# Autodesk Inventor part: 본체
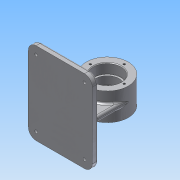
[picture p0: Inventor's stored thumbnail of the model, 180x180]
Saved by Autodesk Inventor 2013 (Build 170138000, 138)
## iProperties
Created: 2019-09
Part Number: 본체
Material: 알루미늄 6061
Document SubType Name: Modeling
Designer: Administrator
Density: 2.71 g/cm^3
Mass: 556.675 g
Surface Area: 495.884 cm^2
Volume: 205.415 cm^3
Author: Administrator
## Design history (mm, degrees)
sketch "스케치1"
  geometry: C1 r 32 at (0, 0); 1 further point
  constraints: 1 centre point, 1 coincident
  dimensions: "d0" = 64 diameter of C1
extrude "돌출1" new body sketch "스케치1" stored distance "d1" = 42; taper "d2" = 0 deg
hole "구멍1" diameter "d5" = 36; stored, may be unused: countersink angle "d9" = 90 deg, drill point angle "d11" = 118 deg; dims "d3" = 10, "d4" = 10, "d6" = 6, "d7" = 42, "d8" = 15, "d10" = 8
sketch "스케치2"
  geometry: C1 r 18 at (0, 0) reference; C2 r 32 at (0, 0) reference; C3 r 21 at (0, 0)
  constraints: 1 centre point, 1 coincident
  dimensions: "d12" = 42 diameter of C3
extrude "돌출2" cut sketch "스케치2" distance "d13" = 15; taper "d14" = 0 deg
fillet "모깎기1" dims "d15" = 0.3
chamfer "모따기1" distance "d16" = 1; stored, may be unused: second distance "d17" = 2, angle "d18" = 45 deg
sketch "스케치3"
  geometry: C1 r 32 at (0, 0) reference; 1 further point
  constraints: 1 vertical alignment
  dimensions: "d19" = 26 distance of C1.centre point (0, 26)
hole "구멍2" sketch "스케치3" at (0, 26) diameter "d20" = 3.242; stored, may be unused: countersink angle "d24" = 90 deg, drill point angle "d26" = 118 deg; dims "d21" = 8, "d22" = 42, "d23" = 15, "d25" = 10
node "작업 평면1"
sketch "스케치4"
  geometry: L1 (62, 63)-(-36, 63); L2 (-36, 63)-(-36, -63); L3 (-36, -63)-(62, -63); L4 (62, -63)-(62, 63); 2 further points
  constraints: 8 end point, 2 parallel, 1 horizontal, 1 horizontal alignment, 1 midpoint, 1 perpendicular
  dimensions: "d31" = 126 distance of L1.end L2.end; "d33" = 62 distance from line of L4 point (0, 0); "d34" = 98 distance of L2.end L3.end
extrude "돌출3" join sketch "스케치4" distance "d35" = 9; taper "d36" = 0 deg
sketch "스케치5"
  geometry: L1 (-32, -4)-(32, -4); L2 (32, -4)-(32, 4); L3 (32, 4)-(-32, 4); L4 (-32, 4)-(-32, -4); L5 (-4, -17)-(4, -17); L6 (4, -17)-(4, 17); L7 (4, 17)-(-4, 17); L8 (-4, 17)-(-4, -17); 3 further points
  constraints: 16 end point, 4 parallel, 2 horizontal, 2 midpoint, 2 perpendicular, 1 horizontal alignment, 1 vertical alignment
  dimensions: "d37" = 8 distance of L2.end L1.end; "d38" = 8 distance of L7.end L6.end; "d39" = 34 distance of L5.end L6.end; "d40" = 17 distance from line of point (0, 0) L5; "d41" = 64 distance of L2.end L3.end; "d56" = 32 distance from line of point (0, 0) L4
extrude "돌출4" join sketch "스케치5" stored distance "d43" = 9; taper "d44" = 0 deg
fillet "모깎기2" dims "d45" = 12
sketch "스케치6"
  geometry: A1 r 12 centre (-50, 51) between (-50, 63) and (-62, 51) reference; A2 r 12 centre (-50, -51) between (-62, -51) and (-50, -63) reference; A3 r 12 centre (24, -51) between (24, -63) and (36, -51) reference; A4 r 12 centre (24, 51) between (36, 51) and (24, 63) reference; 5 further points
  constraints: 4 coincident
hole "구멍3" sketch "스케치6" at (-50, 51), (24, 51), (24, -51), (-50, -51) diameter "d46" = 4.5; stored, may be unused: countersink angle "d50" = 90 deg, drill point angle "d52" = 118 deg; dims "d47" = 8, "d48" = 8, "d49" = 4.4, "d51" = 10
fillet "모깎기3" dims "d53" = 3
fillet "모깎기6" dims "d57" = 3
fillet "모깎기7" dims "d58" = 3
fillet "모깎기8" dims "d59" = 3
sketch "스케치7"
  geometry: L1 (-62, 51)-(-62, -51) reference; 2 further points
  constraints: 1 horizontal alignment, 1 other
  dimensions: "d60" = 10 distance from line of L1 point (-52, 0)
feature "엠보싱1" sketch "스케치7" dims "d61" = 0.5, "d62" = 0
node "솔리드1"
pattern_circular "원형 패턴1" dims angle "d28" = 360 deg
mirror "대칭1"
other parameters: "d30" = -59
